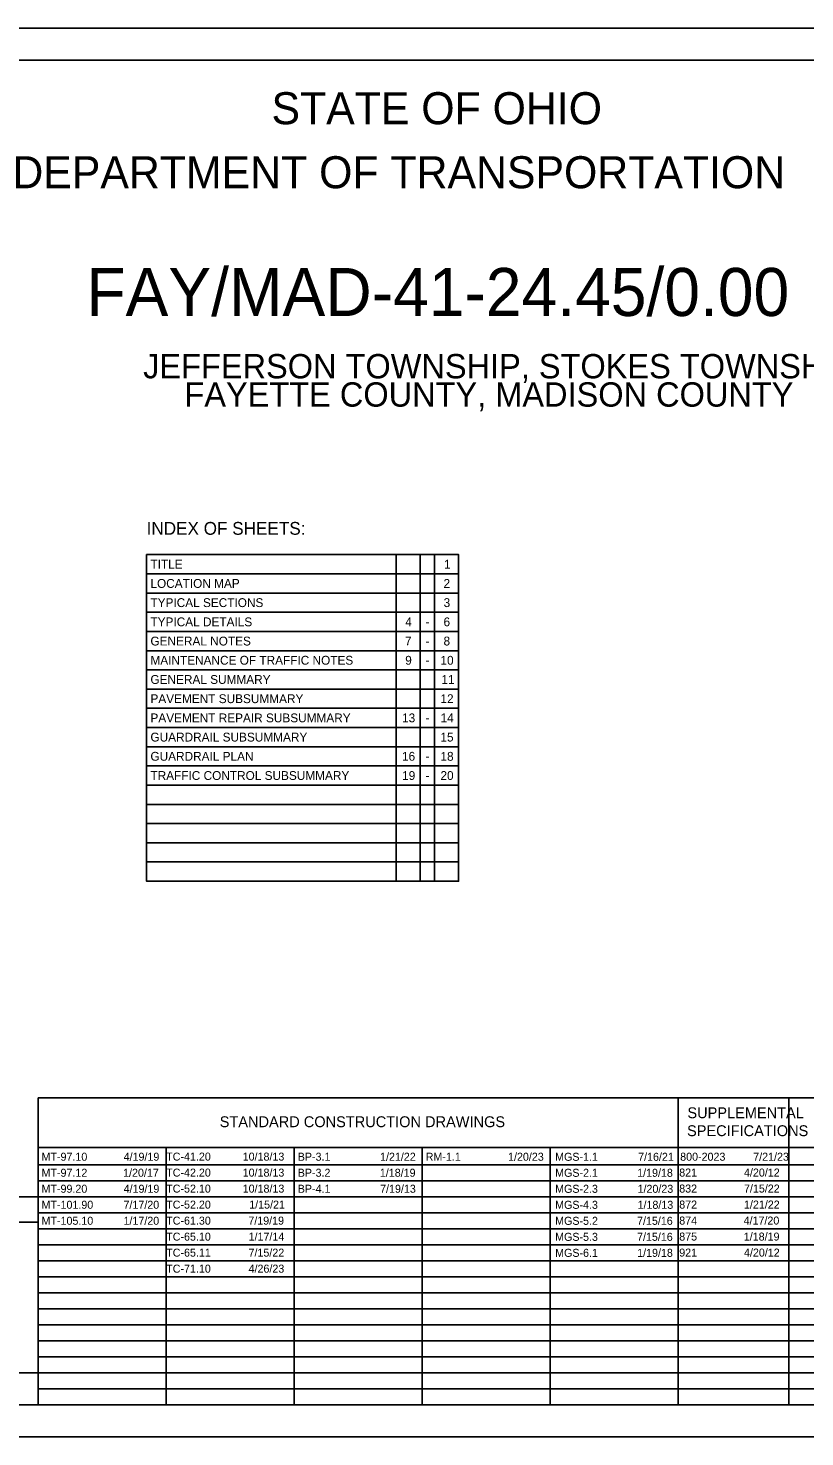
# Model space of a CAD drawing. Extents: x 0 to 34, y 0 to 22.
# Drawn here: x 9.99 to 22.13, y 0 to 22 of the extents above; entities that cross this region are included whole.
import ezdxf

# ---------------------------------------------------------------- set-up
doc = ezdxf.new("R2010")
doc.units = 0
for name, color, linetype in [('Default', 7, 'Continuous'), ('SH_Border', 7, 'Continuous'), ('SH_Cut_Line', 7, 'Continuous'), ('SH_Data', 7, 'Continuous'), ('SH_Text', 7, 'Continuous')]:
    doc.layers.add(name, color=color, linetype=linetype)

msp = doc.modelspace()

# ---------------------------------------------------------------- linework, layer by layer
at = {"layer": 'Default'}
for points in [[(11.844, 13.778), (15.744, 13.778), (15.744, 13.478), (11.844, 13.478)], [(15.744, 13.778), (16.119, 13.778), (16.119, 13.478), (15.744, 13.478)], [(16.119, 13.778), (16.344, 13.778), (16.344, 13.478), (16.119, 13.478)], [(16.344, 13.778), (16.719, 13.778), (16.719, 13.478), (16.344, 13.478)], [(11.844, 13.478), (15.744, 13.478), (15.744, 13.178), (11.844, 13.178)], [(15.744, 13.478), (16.119, 13.478), (16.119, 13.178), (15.744, 13.178)], [(16.119, 13.478), (16.344, 13.478), (16.344, 13.178), (16.119, 13.178)], [(16.344, 13.478), (16.719, 13.478), (16.719, 13.178), (16.344, 13.178)], [(11.844, 13.178), (15.744, 13.178), (15.744, 12.878), (11.844, 12.878)], [(15.744, 13.178), (16.119, 13.178), (16.119, 12.878), (15.744, 12.878)], [(16.119, 13.178), (16.344, 13.178), (16.344, 12.878), (16.119, 12.878)], [(16.344, 13.178), (16.719, 13.178), (16.719, 12.878), (16.344, 12.878)], [(11.844, 12.878), (15.744, 12.878), (15.744, 12.578), (11.844, 12.578)], [(15.744, 12.878), (16.119, 12.878), (16.119, 12.578), (15.744, 12.578)], [(16.119, 12.878), (16.344, 12.878), (16.344, 12.578), (16.119, 12.578)], [(16.344, 12.878), (16.719, 12.878), (16.719, 12.578), (16.344, 12.578)], [(11.844, 12.578), (15.744, 12.578), (15.744, 12.278), (11.844, 12.278)], [(15.744, 12.578), (16.119, 12.578), (16.119, 12.278), (15.744, 12.278)], [(16.119, 12.578), (16.344, 12.578), (16.344, 12.278), (16.119, 12.278)], [(16.344, 12.578), (16.719, 12.578), (16.719, 12.278), (16.344, 12.278)], [(11.844, 12.278), (15.744, 12.278), (15.744, 11.978), (11.844, 11.978)], [(15.744, 12.278), (16.119, 12.278), (16.119, 11.978), (15.744, 11.978)], [(16.119, 12.278), (16.344, 12.278), (16.344, 11.978), (16.119, 11.978)], [(16.344, 12.278), (16.719, 12.278), (16.719, 11.978), (16.344, 11.978)], [(11.844, 11.978), (15.744, 11.978), (15.744, 11.678), (11.844, 11.678)], [(15.744, 11.978), (16.119, 11.978), (16.119, 11.678), (15.744, 11.678)], [(16.119, 11.978), (16.344, 11.978), (16.344, 11.678), (16.119, 11.678)], [(16.344, 11.978), (16.719, 11.978), (16.719, 11.678), (16.344, 11.678)], [(11.844, 11.678), (15.744, 11.678), (15.744, 11.378), (11.844, 11.378)], [(15.744, 11.678), (16.119, 11.678), (16.119, 11.378), (15.744, 11.378)], [(16.119, 11.678), (16.344, 11.678), (16.344, 11.378), (16.119, 11.378)], [(16.344, 11.678), (16.719, 11.678), (16.719, 11.378), (16.344, 11.378)], [(11.844, 11.378), (15.744, 11.378), (15.744, 11.078), (11.844, 11.078)], [(15.744, 11.378), (16.119, 11.378), (16.119, 11.078), (15.744, 11.078)], [(16.119, 11.378), (16.344, 11.378), (16.344, 11.078), (16.119, 11.078)], [(16.344, 11.378), (16.719, 11.378), (16.719, 11.078), (16.344, 11.078)], [(11.844, 11.078), (15.744, 11.078), (15.744, 10.778), (11.844, 10.778)], [(15.744, 11.078), (16.119, 11.078), (16.119, 10.778), (15.744, 10.778)], [(16.119, 11.078), (16.344, 11.078), (16.344, 10.778), (16.119, 10.778)], [(16.344, 11.078), (16.719, 11.078), (16.719, 10.778), (16.344, 10.778)], [(11.844, 10.778), (15.744, 10.778), (15.744, 10.478), (11.844, 10.478)], [(15.744, 10.778), (16.119, 10.778), (16.119, 10.478), (15.744, 10.478)], [(16.119, 10.778), (16.344, 10.778), (16.344, 10.478), (16.119, 10.478)], [(16.344, 10.778), (16.719, 10.778), (16.719, 10.478), (16.344, 10.478)], [(11.844, 10.478), (15.744, 10.478), (15.744, 10.178), (11.844, 10.178)], [(15.744, 10.478), (16.119, 10.478), (16.119, 10.178), (15.744, 10.178)], [(16.119, 10.478), (16.344, 10.478), (16.344, 10.178), (16.119, 10.178)], [(16.344, 10.478), (16.719, 10.478), (16.719, 10.178), (16.344, 10.178)], [(11.844, 10.178), (15.744, 10.178), (15.744, 9.878), (11.844, 9.878)], [(15.744, 10.178), (16.119, 10.178), (16.119, 9.878), (15.744, 9.878)], [(16.119, 10.178), (16.344, 10.178), (16.344, 9.878), (16.119, 9.878)], [(16.344, 10.178), (16.719, 10.178), (16.719, 9.878), (16.344, 9.878)], [(11.844, 9.878), (15.744, 9.878), (15.744, 9.578), (11.844, 9.578)], [(15.744, 9.878), (16.119, 9.878), (16.119, 9.578), (15.744, 9.578)], [(16.119, 9.878), (16.344, 9.878), (16.344, 9.578), (16.119, 9.578)], [(16.344, 9.878), (16.719, 9.878), (16.719, 9.578), (16.344, 9.578)], [(11.844, 9.578), (15.744, 9.578), (15.744, 9.278), (11.844, 9.278)], [(15.744, 9.578), (16.119, 9.578), (16.119, 9.278), (15.744, 9.278)], [(16.119, 9.578), (16.344, 9.578), (16.344, 9.278), (16.119, 9.278)], [(16.344, 9.578), (16.719, 9.578), (16.719, 9.278), (16.344, 9.278)], [(11.844, 9.278), (15.744, 9.278), (15.744, 8.978), (11.844, 8.978)], [(15.744, 9.278), (16.119, 9.278), (16.119, 8.978), (15.744, 8.978)], [(16.119, 9.278), (16.344, 9.278), (16.344, 8.978), (16.119, 8.978)], [(16.344, 9.278), (16.719, 9.278), (16.719, 8.978), (16.344, 8.978)], [(11.844, 8.978), (15.744, 8.978), (15.744, 8.678), (11.844, 8.678)], [(15.744, 8.978), (16.119, 8.978), (16.119, 8.678), (15.744, 8.678)], [(16.119, 8.978), (16.344, 8.978), (16.344, 8.678), (16.119, 8.678)], [(16.344, 8.978), (16.719, 8.978), (16.719, 8.678), (16.344, 8.678)]]:
    msp.add_lwpolyline(points, close=True, dxfattribs=at)
at = {"layer": 'SH_Border'}
msp.add_lwpolyline([(1.5, 21.5), (33.5, 21.5), (33.5, 0.5), (1.5, 0.5)], close=True, dxfattribs=at)
at = {"layer": 'SH_Cut_Line'}
msp.add_lwpolyline([(0, 0), (34, 0), (34, 22), (0, 22)], close=True, dxfattribs=at)
at = {"layer": 'SH_Data'}
for p, q in [((10.15, 5.292), (23.6, 5.292)), ((10.15, 0.5), (10.15, 5.292)), ((20.15, 0.5), (20.15, 5.292)), ((21.875, 0.5), (21.875, 5.292)), ((10.15, 4.521), (23.6, 4.521)), ((12.15, 0.5), (12.15, 4.521)), ((14.15, 0.5), (14.15, 4.521)), ((16.15, 0.5), (16.15, 4.521)), ((18.15, 0.5), (18.15, 4.521)), ((10.15, 4.25), (23.6, 4.25)), ((10.15, 4), (23.6, 4)), ((10.15, 3.75), (7.35, 3.75)), ((10.15, 3.75), (23.6, 3.75)), ((10.15, 0.5), (10.15, 3.75)), ((10.15, 3.35), (7.35, 3.35)), ((10.15, 3.5), (23.6, 3.5)), ((10.15, 3.25), (23.6, 3.25)), ((10.15, 3), (23.6, 3)), ((10.15, 2.75), (23.6, 2.75)), ((10.15, 2.5), (23.6, 2.5)), ((10.15, 2.25), (23.6, 2.25)), ((10.15, 2), (23.6, 2)), ((10.15, 1.75), (23.6, 1.75)), ((10.15, 1.5), (23.6, 1.5)), ((10.15, 1.25), (23.6, 1.25)), ((10.15, 1), (23.6, 1)), ((10.15, 0.75), (23.6, 0.75)), ((10.15, 0.5), (7.35, 0.5))]:
    msp.add_line(p, q, dxfattribs=at)
msp.add_lwpolyline([(10.15, 0.5), (10.15, 1), (7.35, 1), (7.35, 0.5)], close=True, dxfattribs=at)

# ---------------------------------------------------------------- texts
at = {"layer": 'Default'}
for s, height, p in [('TITLE', 0.138, (11.904, 13.559)), ('1', 0.138, (16.49, 13.559)), ('LOCATION MAP', 0.138, (11.904, 13.259)), ('2', 0.138, (16.483, 13.259)), ('TYPICAL SECTIONS', 0.138, (11.904, 12.959)), ('3', 0.138, (16.484, 12.959)), ('TYPICAL DETAILS', 0.138, (11.904, 12.659)), ('4', 0.138, (15.885, 12.659)), ('6', 0.138, (16.483, 12.659)), ('-', 0.138, (16.203, 12.659)), ('GENERAL NOTES', 0.138, (11.904, 12.359)), ('7', 0.138, (15.88, 12.359)), ('-', 0.138, (16.203, 12.359)), ('8', 0.138, (16.483, 12.359)), ('MAINTENANCE OF TRAFFIC NOTES', 0.138, (11.904, 12.059)), ('9', 0.138, (15.884, 12.059)), ('-', 0.138, (16.203, 12.059)), ('10', 0.138, (16.435, 12.059)), ('GENERAL SUMMARY', 0.138, (11.904, 11.759)), ('11', 0.138, (16.449, 11.759)), ('PAVEMENT SUBSUMMARY', 0.138, (11.904, 11.459)), ('12', 0.138, (16.435, 11.459)), ('PAVEMENT REPAIR SUBSUMMARY', 0.138, (11.904, 11.159)), ('13', 0.138, (15.835, 11.159)), ('14', 0.138, (16.436, 11.159)), ('-', 0.138, (16.203, 11.159)), ('GUARDRAIL SUBSUMMARY', 0.138, (11.904, 10.859)), ('15', 0.138, (16.434, 10.859)), ('GUARDRAIL PLAN', 0.138, (11.904, 10.559)), ('16', 0.138, (15.834, 10.559)), ('-', 0.138, (16.203, 10.559)), ('18', 0.138, (16.435, 10.559)), ('TRAFFIC CONTROL SUBSUMMARY', 0.138, (11.904, 10.259)), ('19', 0.138, (15.836, 10.259)), ('20', 0.138, (16.435, 10.259)), ('-', 0.138, (16.203, 10.259)), ('MT-97.10', 0.125, (10.202, 4.312)), ('4/19/19', 0.125, (11.485, 4.312)), ('TC-41.20', 0.125, (12.15, 4.314)), ('10/18/13', 0.125, (13.345, 4.314)), ('BP-3.1', 0.125, (14.205, 4.312)), ('1/21/22', 0.125, (15.491, 4.312)), ('RM-1.1', 0.125, (16.204, 4.312)), ('1/20/23', 0.125, (17.491, 4.312)), ('MGS-1.1', 0.125, (18.226, 4.311)), ('7/16/21', 0.125, (19.523, 4.311)), ('800-2023', 0.125, (20.18, 4.312)), ('7/21/23', 0.125, (21.321, 4.312)), ('MT-97.12', 0.125, (10.202, 4.062)), ('1/20/17', 0.125, (11.477, 4.062)), ('TC-42.20', 0.125, (12.15, 4.064)), ('10/18/13', 0.125, (13.345, 4.064)), ('BP-3.2', 0.125, (14.205, 4.062)), ('1/18/19', 0.125, (15.488, 4.062)), ('MGS-2.1', 0.125, (18.226, 4.061)), ('1/19/18', 0.125, (19.508, 4.061)), ('821', 0.125, (20.165, 4.065)), ('4/20/12', 0.125, (21.177, 4.065)), ('MT-99.20', 0.125, (10.202, 3.812)), ('4/19/19', 0.125, (11.485, 3.812)), ('TC-52.10', 0.125, (12.15, 3.814)), ('10/18/13', 0.125, (13.345, 3.814)), ('BP-4.1', 0.125, (14.205, 3.812)), ('7/19/13', 0.125, (15.492, 3.812)), ('MGS-2.3', 0.125, (18.226, 3.811)), ('1/20/23', 0.125, (19.514, 3.811)), ('832', 0.125, (20.165, 3.815)), ('7/15/22', 0.125, (21.177, 3.815)), ('MT-101.90', 0.125, (10.202, 3.562)), ('7/17/20', 0.125, (11.483, 3.562)), ('TC-52.20', 0.125, (12.15, 3.564)), ('1/15/21', 0.125, (13.447, 3.564)), ('MGS-4.3', 0.125, (18.226, 3.561)), ('1/18/13', 0.125, (19.514, 3.561)), ('872', 0.125, (20.165, 3.565)), ('1/21/22', 0.125, (21.177, 3.565)), ('MT-105.10', 0.125, (10.202, 3.312)), ('1/17/20', 0.125, (11.483, 3.312)), ('TC-61.30', 0.125, (12.15, 3.314)), ('7/19/19', 0.125, (13.433, 3.314)), ('MGS-5.2', 0.125, (18.226, 3.311)), ('7/15/16', 0.125, (19.506, 3.311)), ('874', 0.125, (20.165, 3.315)), ('4/17/20', 0.125, (21.171, 3.315)), ('TC-65.10', 0.125, (12.15, 3.064)), ('1/17/14', 0.125, (13.437, 3.064)), ('MGS-5.3', 0.125, (18.226, 3.061)), ('7/15/16', 0.125, (19.506, 3.061)), ('875', 0.125, (20.165, 3.065)), ('1/18/19', 0.125, (21.174, 3.065)), ('TC-65.11', 0.125, (12.15, 2.814)), ('7/15/22', 0.125, (13.436, 2.814)), ('MGS-6.1', 0.125, (18.226, 2.811)), ('1/19/18', 0.125, (19.508, 2.811)), ('921', 0.125, (20.165, 2.815)), ('4/20/12', 0.125, (21.177, 2.815)), ('TC-71.10', 0.125, (12.15, 2.564)), ('4/26/23', 0.125, (13.437, 2.564))]:
    msp.add_text(s, height=height, dxfattribs=at).set_placement(p)
at = {"layer": 'SH_Text'}
for s, height, p in [('STATE OF OHIO', 0.5, (13.795, 20.5)), ('DEPARTMENT OF TRANSPORTATION', 0.5, (9.747, 19.5)), ('FAY/MAD-41-24.45/0.00', 0.75, (10.902, 17.505)), ('JEFFERSON TOWNSHIP, STOKES TOWNSHIP', 0.38, (11.79, 16.531)), ('FAYETTE COUNTY, MADISON COUNTY', 0.38, (12.435, 16.089)), ('INDEX OF SHEETS:', 0.2, (11.844, 14.088)), ('SUPPLEMENTAL', 0.17, (20.293, 4.976)), ('STANDARD CONSTRUCTION DRAWINGS', 0.17, (12.986, 4.836)), ('SPECIFICATIONS', 0.17, (20.287, 4.696))]:
    msp.add_text(s, height=height, dxfattribs=at).set_placement(p)

doc.saveas('drawing.dxf')
